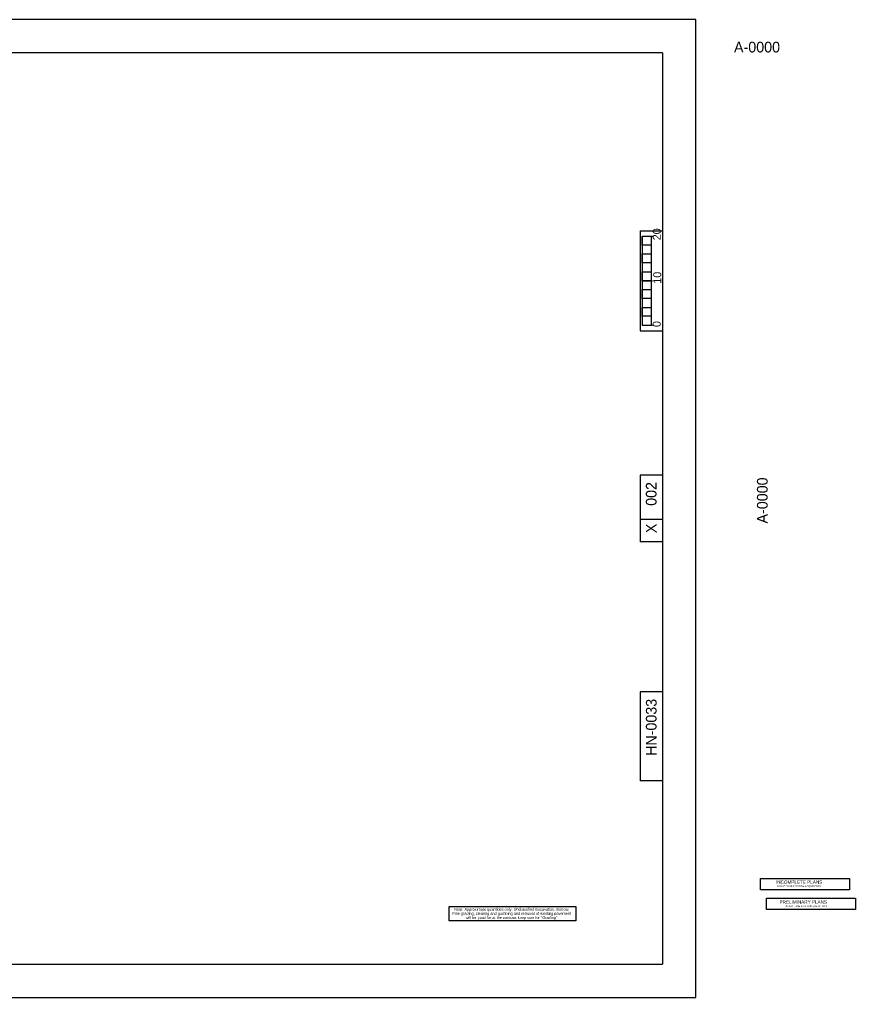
# Model space of a CAD drawing. Extents: x -2.69 to 3.13, y 0 to 1.83.
# Drawn here: x 1.566 to 3.133, y 0 to 1.833 of the extents above; entities that cross this region are included whole.
import ezdxf

# ---------------------------------------------------------------- set-up
doc = ezdxf.new("R2010")
doc.units = 0
for name, color, linetype in [('P_NCDOT_XS_Sheet_Alignment_Station_Label', 7, 'Continuous'), ('P_NCDOT_XS_Sheet_Grid_Border', 7, 'Continuous'), ('Sheet_Grid_Major', 7, 'Continuous'), ('Sheet_Grid_Middle', 7, 'Continuous'), ('Sheet_Grid_Minor', 7, 'Continuous')]:
    doc.layers.add(name, color=color, linetype=linetype)

msp = doc.modelspace()

# ---------------------------------------------------------------- linework, layer by layer
at = {"layer": 'P_NCDOT_XS_Sheet_Alignment_Station_Label'}
for p, q in [((2.7332, 1.4272), (2.7521, 1.4272)), ((2.7332, 1.4272), (2.7332, 1.2605)), ((2.7416, 1.4272), (2.7503, 1.4272)), ((2.7499, 1.4272), (2.7499, 1.2605)), ((2.7332, 1.3438), (2.7521, 1.3438)), ((2.7332, 1.2605), (2.7521, 1.2605)), ((2.7416, 1.2605), (2.7503, 1.2605))]:
    msp.add_line(p, q, dxfattribs=at)
for points in [[(2.7332, 1.4272), (2.7499, 1.4272), (2.7499, 1.4105), (2.7332, 1.4105)], [(2.7332, 1.3938), (2.7499, 1.3938), (2.7499, 1.3772), (2.7332, 1.3772)], [(2.7332, 1.3605), (2.7499, 1.3605), (2.7499, 1.3438), (2.7332, 1.3438)], [(2.7332, 1.3272), (2.7499, 1.3272), (2.7499, 1.3105), (2.7332, 1.3105)], [(2.7332, 1.2938), (2.7499, 1.2938), (2.7499, 1.2772), (2.7332, 1.2772)], [(2.9549, 0.2232), (3.1216, 0.2232), (3.1216, 0.202), (2.9549, 0.202)], [(2.966, 0.1859), (3.1326, 0.1859), (3.1326, 0.1647), (2.966, 0.1647)], [(2.3716, 0.1704), (2.6084, 0.1704), (2.6084, 0.1436), (2.3716, 0.1436)]]:
    msp.add_lwpolyline(points, close=True, dxfattribs=at)
at = {"layer": 'Sheet_Grid_Major'}
for p, q in [((2.8333, 1.8333), (0, 1.8333)), ((2.8333, 0), (2.8333, 1.8333)), ((0, 0), (2.8333, 0))]:
    msp.add_line(p, q, dxfattribs=at)
for centre in [(2.7499, 1.3437), (2.7499, 0.9375), (2.7499, 0.875), (2.75, 0.4897)]:
    msp.add_circle(centre, 0.0001, dxfattribs=at)
at = {"layer": 'Sheet_Grid_Minor'}
for p, q in [((2.7708, 1.7708), (0.0625, 1.7708)), ((2.7708, 1.7708), (2.7708, 0.0625)), ((2.7292, 1.4375), (2.7292, 1.25)), ((2.7292, 1.4375), (2.7708, 1.4375)), ((2.7292, 1.25), (2.7708, 1.25)), ((2.7292, 0.9792), (2.7292, 0.8542)), ((2.7708, 0.9792), (2.7292, 0.9792)), ((2.7708, 0.8958), (2.7292, 0.8958)), ((2.7708, 0.8542), (2.7292, 0.8542)), ((2.7292, 0.5729), (2.7292, 0.4062)), ((2.7708, 0.5729), (2.7292, 0.5729)), ((2.7708, 0.4062), (2.7292, 0.4062)), ((0.0625, 0.0625), (2.7708, 0.0625))]:
    msp.add_line(p, q, dxfattribs=at)

# ---------------------------------------------------------------- texts
at = {"layer": 'P_NCDOT_XS_Sheet_Alignment_Station_Label'}
for s, p in [('20', (2.7678, 1.4196)), ('10', (2.7688, 1.3382)), ('0', (2.7677, 1.2569))]:
    msp.add_text(s, height=0.015, rotation=90, dxfattribs=at).set_placement(p)
for s, height, p in [('INCOMPLETE PLANS', 0.00625, (2.9837, 0.2131)), ('DO NOT USE FOR R/W ACQUISITION', 0.003375, (2.9858, 0.2068)), ('Note: Approximate quantities only. Unclassified Excavation, Borrow, ', 0.0052, (2.3809, 0.1626)), ('PRELIMINARY PLANS', 0.00625, (2.9903, 0.1758)), ('DO NOT USE FOR CONSTRUCTION', 0.003375, (3.0001, 0.1695)), ('Fine grading, clearing and grubbing and removal of existing pavement ', 0.0052, (2.3774, 0.1548)), ('will be  paid for at the contract lump sum for "Grading". ', 0.0052, (2.4023, 0.147))]:
    msp.add_text(s, height=height, dxfattribs=at).set_placement(p)
at = {"layer": 'P_NCDOT_XS_Sheet_Grid_Border'}
for s, p in [('002', (2.7599, 0.9217)), ('X', (2.7599, 0.8704))]:
    msp.add_text(s, height=0.02, rotation=90, dxfattribs=at).set_placement(p)
at = {"layer": 'Sheet_Grid_Middle'}
msp.add_text('A-0000', height=0.02, dxfattribs=at).set_placement((2.9051, 1.7717))
for s, p in [('A-0000', (2.9681, 0.8886)), ('HN-0033', (2.76, 0.4528))]:
    msp.add_text(s, height=0.02, rotation=90, dxfattribs=at).set_placement(p)

doc.saveas('drawing.dxf')
